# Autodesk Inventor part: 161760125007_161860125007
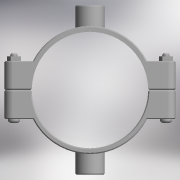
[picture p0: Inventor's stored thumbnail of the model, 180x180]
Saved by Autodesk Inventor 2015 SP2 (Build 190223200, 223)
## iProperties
Created: 2017-05
Part Number: 161760125007_161860125007
Material: Generic
Description: PLASSON DOUBLE SADDLE 125-3/4"
Document SubType Name: Modeling
Designer: KIM
Density: 1 g/cm^3
Appearance: Default
Author: KIM
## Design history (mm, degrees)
derived "16176.ipt"
feature "Solid1::16176.ipt"
feature "Solid2::16176.ipt"
tag "TaggingFeature1"
body "Solid1"
body "Solid2"
other parameters: "d0" = 137.5, "d1" = 184, "d2" = 62.5, "d3" = 125, "d4" = 124, "d5" = 0, "d6" = 9.2, "d7" = 184, "d8" = 0.1, "d10" = 0, "d11" = 1.25, "d20" = 1.25, "d23" = 1.25, "d36" = 13, "d37" = 10.4, "d38" = 70.5, "d39" = 0, "d40" = 3, "d41" = 5, "d42" = 0, "d43" = 8, "d44" = 3, "d45" = 0, "d46" = 1.25, "d52" = 24.117, "d53" = 19, "d54" = 0, "d57" = 0, "d58" = 135, "d60" = 0, "d62" = 13, "d63" = 10.4, "d66" = 103.2, "d67" = 182, "d68" = 31.3521, "d69" = 24.117, "d70" = 19, "d71" = 0, "d74" = 0, "d75" = 1.25, "d_" = 125, "G_" = 24.117, "A_" = 91, "L_" = 184, "L_1" = 124, "l_2" = 19
